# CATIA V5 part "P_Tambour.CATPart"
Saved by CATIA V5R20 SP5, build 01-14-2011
Part number: Tambour
Bounding box of the stored display mesh (mm): x -136.137 to 136.137, y 162.727 to 435, z -10 to 150
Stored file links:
  U:\2A\CFAO\dossier sans titre\P_Tambour.CATPart
  U:\2A\CFAO\dossier sans titre\Gouvernail.CATProduct
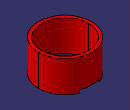
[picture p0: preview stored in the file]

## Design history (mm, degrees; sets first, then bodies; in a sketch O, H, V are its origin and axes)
External parameters (linked from other documents)
  External.Larg_Totale = 450 mm
Set1
  Point1 "Point.24": linked copy from another document
  Point2 "Point.25": linked copy from another document
Body1 (main body)
  Sketch1 on xy-plane, origin (0, 0, 0), H (1, 0, 0), V (0, 1, 0)
    circle A1 centre (0, 298.8638) radius 121.1365
    point P1 (0, 298.8638)
    reference projected point E1 (0, 298.8638) from Point1
    reference projected point E2 (0, 177.7273) from Point2
    circle A2 centre (0, 298.8638) radius 136.1365
    distance A1 A2 = 15
    coincidence: P1 E1, A1 E2
  Pad1: profile Sketch1, direction (0, 0, 1), length 150, opposite side length 10
  Sketch2 on xy-plane, origin (0, 0, 0), H (1, 0, 0), V (0, 1, 0)
    line L1 (-50, 500) -> (50, 500)
    line L2 (50, 500) -> (50, 100)
    line L3 (50, 100) -> (-50, 100)
    line L4 (-50, 100) -> (-50, 500)
    length L3 = 100 {= (100/450)*External.Larg_Totale}
    length L2 = 400 {= (400/450)*External.Larg_Totale}
    distance L3 H = 100 {= Sketch2.length(L3)}
    distance L2 V = 50 {= Sketch2.length(L3) /2}
    horizontal: L1 H, L3 H
    vertical: L2 V, L4 V
  Pocket1: profile Sketch2, direction (0, 0, -1), length 10, opposite side length 5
